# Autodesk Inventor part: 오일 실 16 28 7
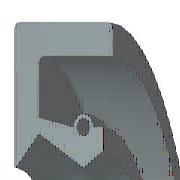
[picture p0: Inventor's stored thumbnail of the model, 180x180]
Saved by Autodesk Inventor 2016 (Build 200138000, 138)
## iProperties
Created: 2012-02
Part Number: 오일 실 16 28 7
Material: 고무
Description: 오일-실
Document SubType Name: Modeling
Standard: KS B 2804
Designer: mduedu
Standards Organization: KS
Language: ko-KR
Size Designation: D - 16 28 7
Categories: <MemberInstance><Categories><Category DisplayName="샤프트 부품" InternalName="7f7aeb1f-a693-4053-b835-cee3144e0d98" Mnemonic="SHFT"><Category DisplayName="실링" Intern
Density: 0.93 g/cm^3
Appearance: 고무 - 검은색 - 버전 1.1
IsCustomPart: 1
Author: mduedu
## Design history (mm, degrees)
revolve "본체" stored, may be unused: angle "d17" = 90 deg
revolve "스프링1" stored, may be unused: angle "d18" = 90 deg
fillet "모깎기3" dims "d43" = 0.5
body "Solid1"
sketch "스케치1"
  geometry: L1 (0, 14)-(7, 14); L2 (7, 12.25)-(1.75, 12.25); L3 (1.75, 9.75)-(4.9, 8); L4 (4.9, 8)-(0, 8); L5 (0, 0)-(9.586, 0) reference; L6 (4.9, 8)-(6.3, 8.875); L7 (0, 18)-(0, -3) reference; L8 (-1.941, 0)-(11.507, 0) reference; L9 (4.2, 10.1)-(1.75, 10.59); L10 (1.75, 10.59)-(1.75, 12.25); L11 (0, 14)-(0, 8.088); L12 (4.9, 8)-(0, 8); L13 (1.75, 9.75)-(0.152, 8.028); L14 (7, 14)-(7, 12.25); L15 (5.6, 10.1)-(6.3, 10.1); L16 (6.3, 10.1)-(6.3, 8.875); C1 r 0.455 at (4.9, 10.1); A1 r 0.7 centre (4.9, 10.1) between (5.6, 10.1) and (4.2, 10.1); A2 r 0.088 centre (0.088, 8.088) between (0, 8.088) and (0.152, 8.028); 1 further point
  constraints: 28 end point, 5 horizontal alignment, 5 point on line, 4 point on circle, 4 vertical alignment, 3 centre point, 3 tangent, 2 collinear, 2 horizontal, 2 perpendicular, 1 coincident, 1 parallel
  dimensions: "d0" = 28 diameter of L1 L5 (= SD2); "d1" = 1.75 distance of L1.end L2.start (= SD); "d2" = 0.91 diameter of C1 (= SPDI); "d3" = 1.4 diameter of A1 (= SPDA); "d4" = 16 diameter of L3.end L5 (= NND); "d5" = 19.5 diameter of L3.start L5 (= TKDM); "d7" = 21.18 diameter of L9.end L5 (= TKDM + 0.24 x SWDT); "d8" = 1.75 distance between parallel lines of L11 L10 (= SD); "d9" = 4.9 distance from line of L11 C1.centre (= SPDST); "d10" = 20.2 diameter of C1.centre L5 (= HLDM); "d11" = 0.0875 radius of A2 (= 0.25 x LAB); "d12" = 6.3 distance between parallel lines of L11 L16 (= SDI); "d13" = 17.75 diameter of L6.end L5 (= ABDM); "d14" = 7 distance from line of L11 L1.end (= SWDT)
fillet "모깎기1" dims "d6" = 0.3 (= RR)
other parameters: "SD2" = 28 [user parameter; used in 1 equation term], "SWDT" = 7 [user parameter; used in 2 equation terms], "RR" = 0.3 [user parameter; used in 1 equation term], "SD" = 1.75 [user parameter; used in 2 equation terms], "NND" = 16 [user parameter; used in 1 equation term], "SPDA" = 1.4 [user parameter; used in 1 equation term], "SPDI" = 0.91 [user parameter; used in 1 equation term], "TKDM" = 19.5 [user parameter; used in 2 equation terms], "HLDM" = 20.2 [user parameter; used in 1 equation term], "ABDM" = 17.75 [user parameter; used in 1 equation term], "SDI" = 6.3 [user parameter; used in 1 equation term], "SPDST" = 4.9 [user parameter; used in 1 equation term], "LAB" = 0.35 [user parameter; used in 1 equation term], "d15" = 0, "d16" = 0, "d19" = 0
